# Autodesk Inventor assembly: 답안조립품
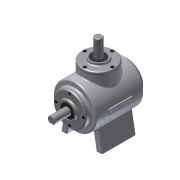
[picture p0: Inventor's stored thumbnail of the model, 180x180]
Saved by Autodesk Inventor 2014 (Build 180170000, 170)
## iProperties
Created: 2015-01
Part Number: 답안조립품
Document SubType Name: Assembly
Designer: L-10
Author: L-10
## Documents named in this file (15)
- C:\Users\L-10\Desktop\450106V1011\답안조립품.iam
- C:\Users\L-10\Desktop\450106V1011\1본체.ipt
- C:\Users\L-10\Desktop\450106V1011\커버2.ipt
- C:\Users\L-10\Desktop\450106V1011\M4.ipt
- C:\Users\L-10\Desktop\450106V1011\커버.ipt
- C:\Users\L-10\Desktop\450106V1011\베어링 6203.ipt
- C:\Users\L-10\Desktop\450106V1011\오일실.ipt
- C:\Users\L-10\Desktop\450106V1011\서브 베벨기어.ipt
- C:\Users\L-10\Desktop\450106V1011\서브 축.ipt
- 서브 축.ipt
- C:\Users\L-10\Desktop\450106V1011\키 4x4.ipt
- C:\Users\L-10\Desktop\450106V1011\키 5x5.ipt
- C:\Users\L-10\Desktop\450106V1011\메인 축.ipt
- 메인 축.ipt
- C:\Users\L-10\Desktop\450106V1011\메인 베벨기어.ipt
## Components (13 placed, 2 different names)
1. 1본체:1
2. M4:1
3. M4:2
4. M4:3
5. M4:4
6. M4:6
7. M4:7
8. M4:8
9. M4:9
10. M4:5
11. M4:10
12. M4:11
13. M4:12
## Named parameters: d15_d5 = 0, d16_d6 = 0
